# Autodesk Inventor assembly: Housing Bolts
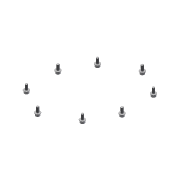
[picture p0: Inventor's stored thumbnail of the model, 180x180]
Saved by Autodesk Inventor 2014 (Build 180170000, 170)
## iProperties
Created: 2011-01
Part Number: Housing Bolts
Document SubType Name: Assembly
Designer: Beta-8540w
ClientObjectVersion: 1
Author: Beta-8540w
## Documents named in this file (3)
- C:\Inventor 2014 Essentials\Assemblies\Chapter 09\Design Accelerators\Bolted Connection c09-01.iam
- C:\Inventor 2014 Essentials\Content Center Files\en-US\ISO 7089\ISO 7089 - 4 - 140 HV.ipt
- C:\Inventor 2014 Essentials\Content Center Files\en-US\ISO 4762\ISO 4762 - M4 x 10ISO.ipt
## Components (16 placed, 2 different names)
1. ISO 7089 4 - 140 HV:1
2. ISO 4762 M4 x 10:1
3. ISO 4762 M4 x 10:2
4. ISO 4762 M4 x 10:3
5. ISO 4762 M4 x 10:4
6. ISO 4762 M4 x 10:5
7. ISO 4762 M4 x 10:6
8. ISO 4762 M4 x 10:7
9. ISO 4762 M4 x 10:8
10. ISO 7089 4 - 140 HV:2
11. ISO 7089 4 - 140 HV:3
12. ISO 7089 4 - 140 HV:4
13. ISO 7089 4 - 140 HV:5
14. ISO 7089 4 - 140 HV:6
15. ISO 7089 4 - 140 HV:7
16. ISO 7089 4 - 140 HV:8
